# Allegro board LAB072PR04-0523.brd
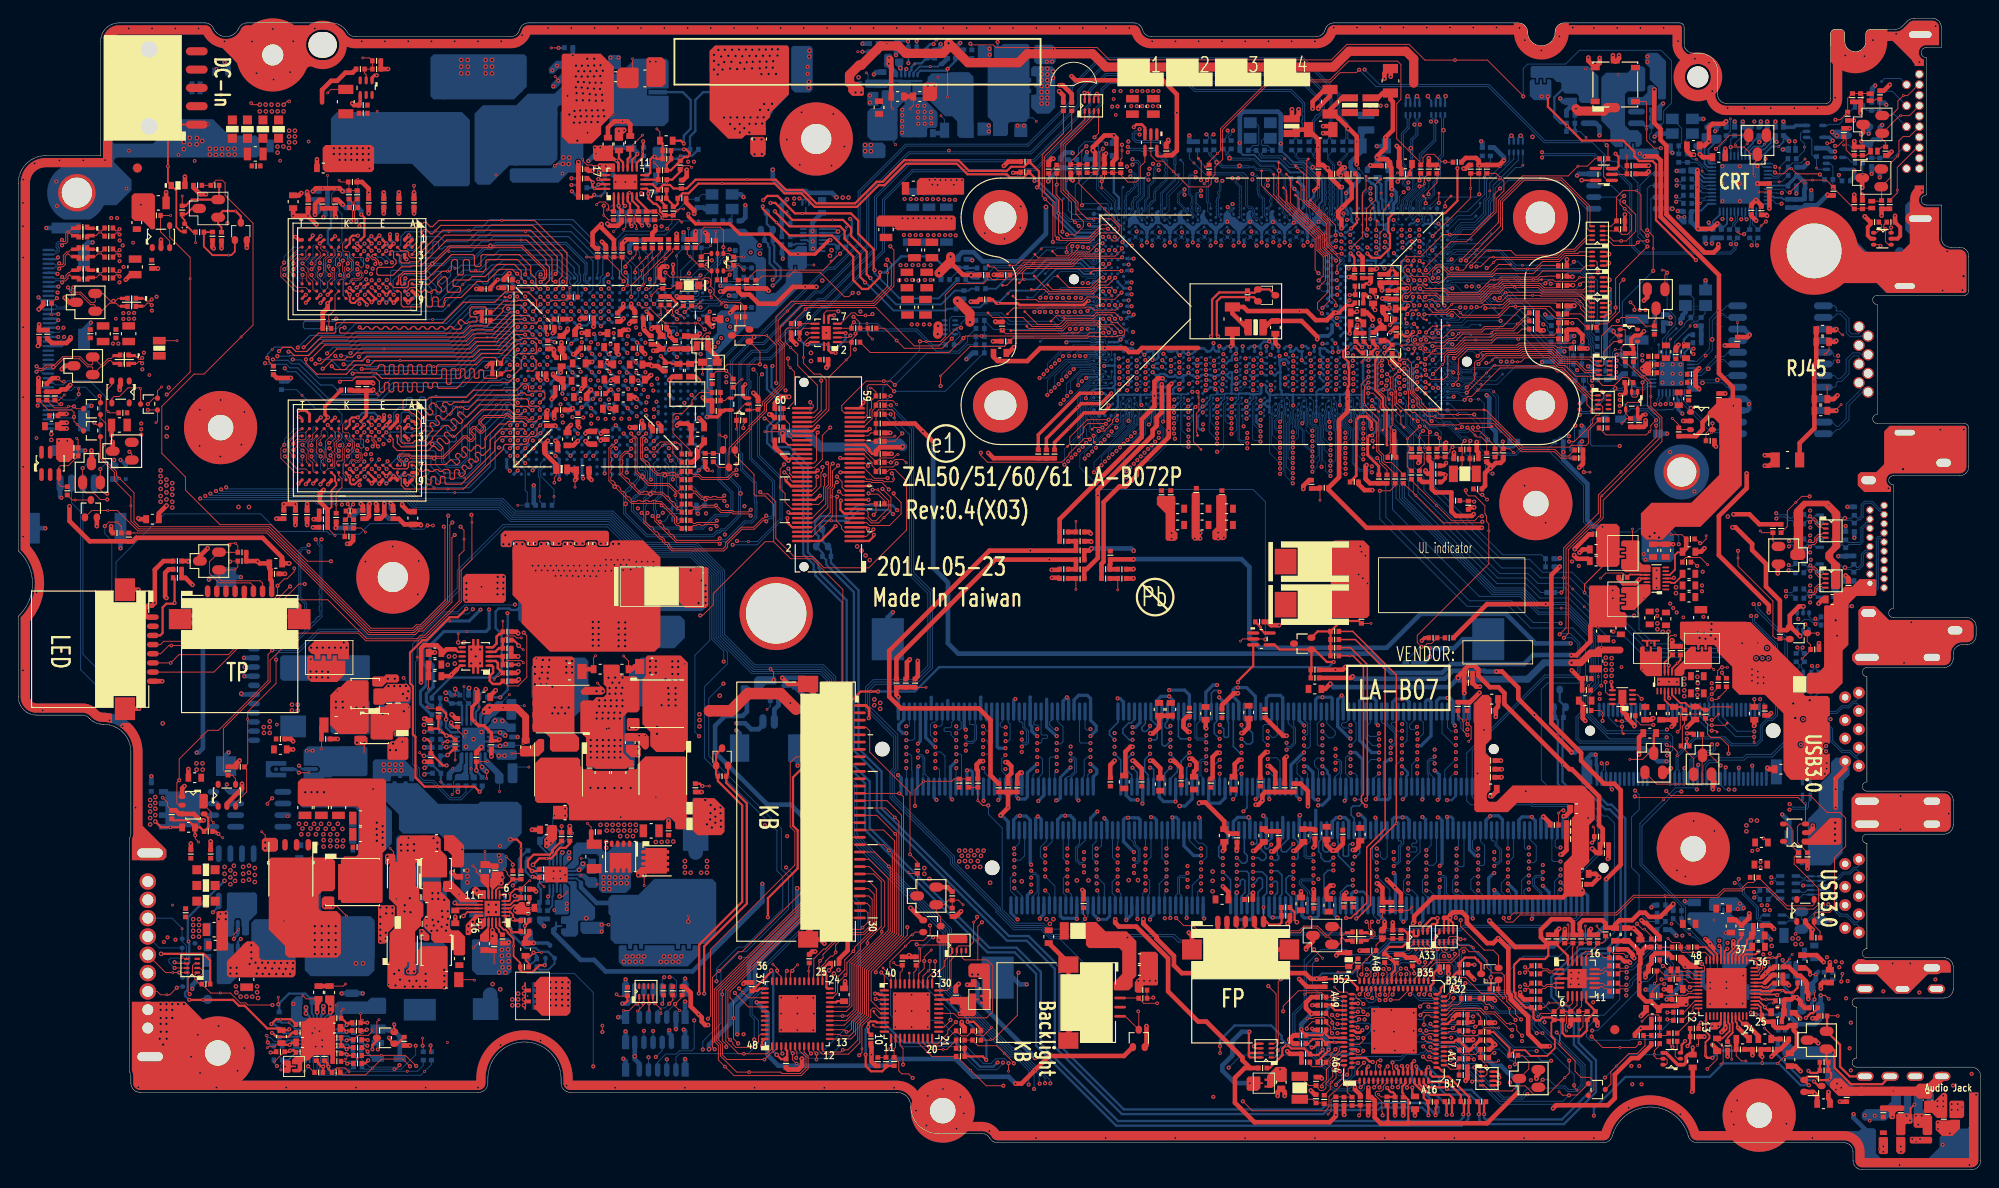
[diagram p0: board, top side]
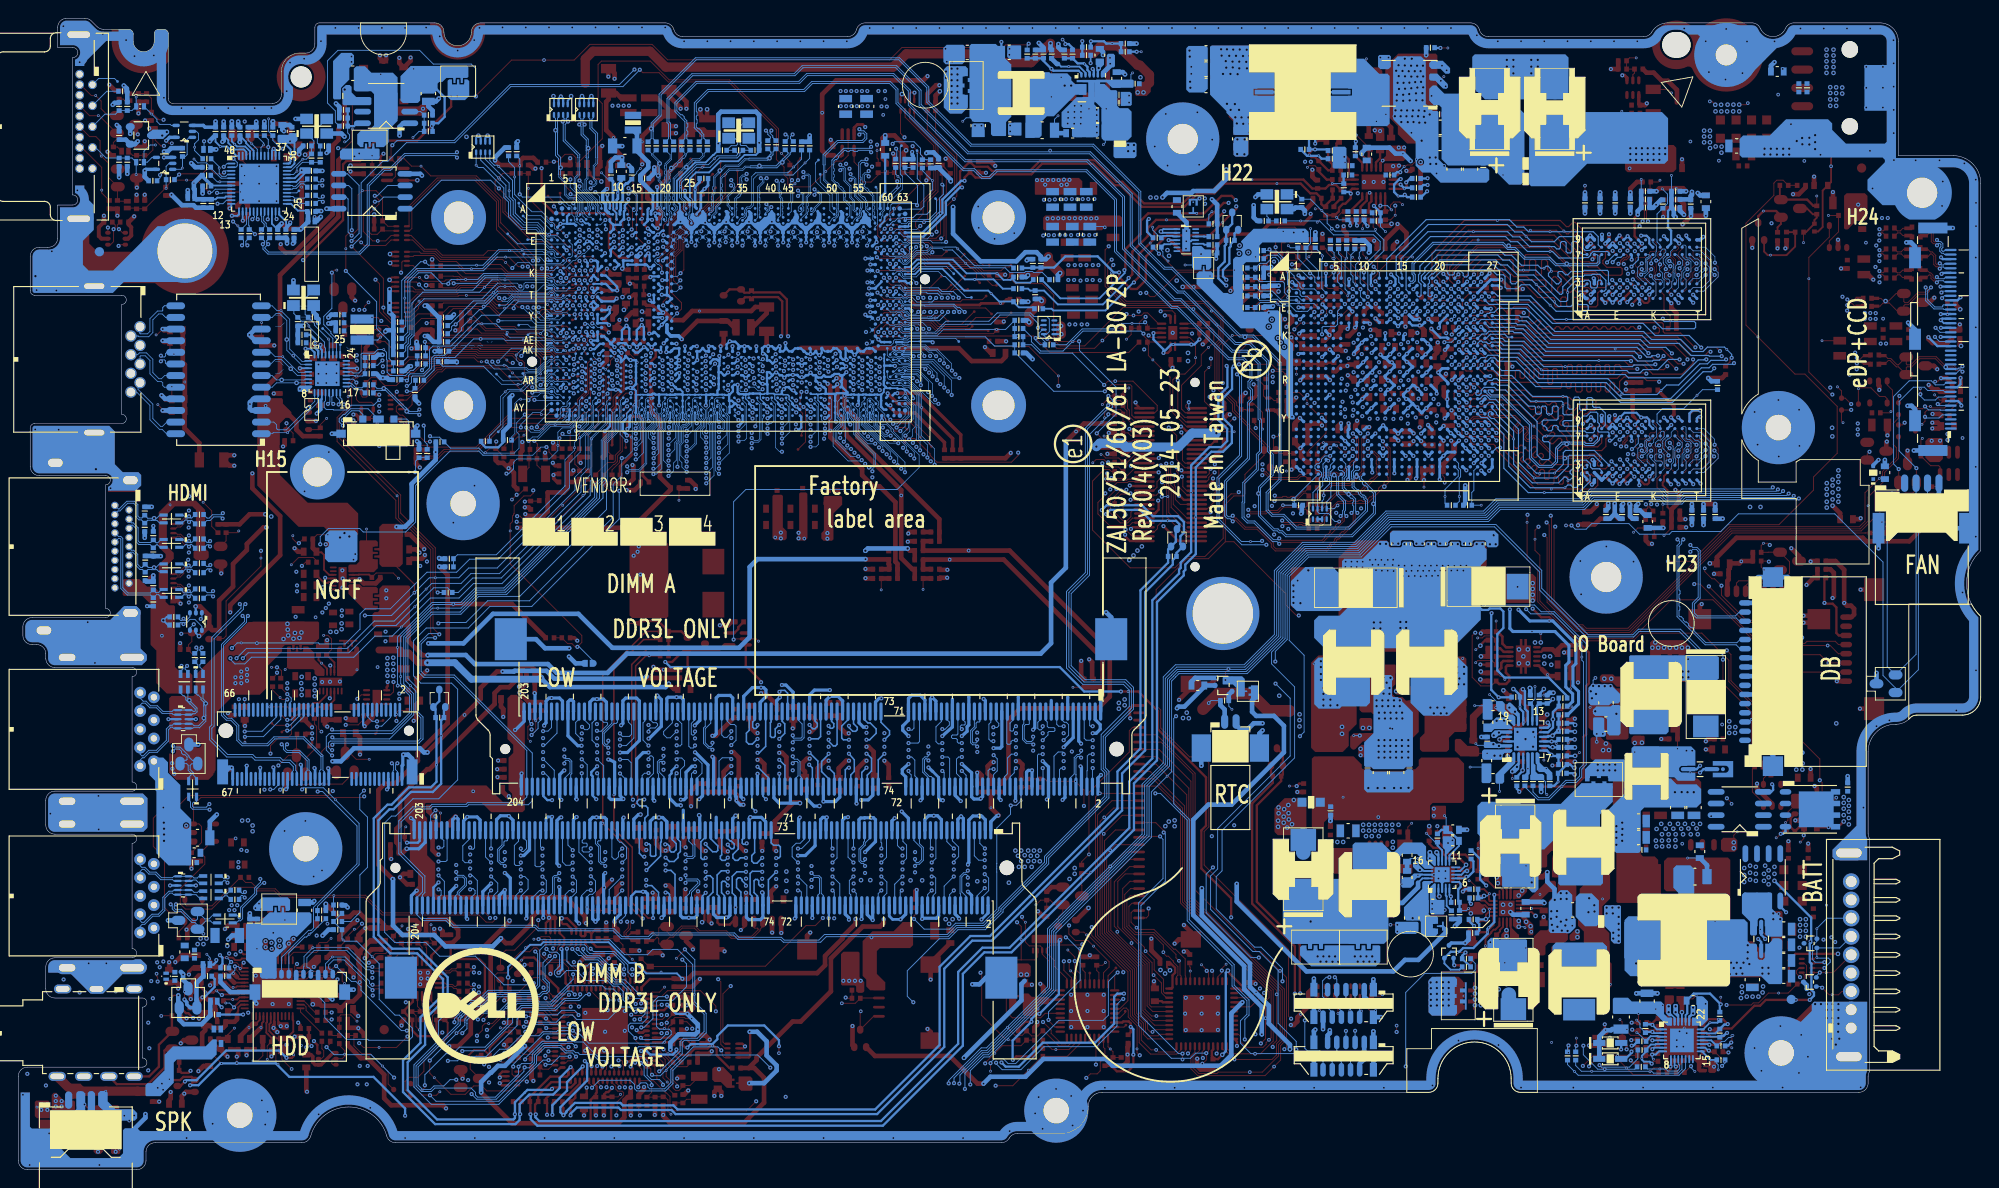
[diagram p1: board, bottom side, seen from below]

Outline 214.4 x 125.75 mm; copper layers: TOP, GND1, IN1, VCC, IN2, IN3, GND2, BOTTOM. Coordinates in mm from the lower left corner of the outline.
Outline path: 0,107.75 arc(0.88,109.87) 3,110.75 9,110.75 9,123.25 arc(9.59,124.66) 11,125.25 20.41,125.25 arc(20.96,125.09) 21.33,124.65 arc(22.7,123.75) 24.07,124.65 arc(24.44,125.09) 24.99,125.25 34.2,125.25 arc(35.2,124.98) 35.93,124.25 arc(36.3,123.88) 36.8,123.75 53.8,123.75 arc(54.41,123.96) 54.77,124.5 arc(55.12,125.04) 55.74,125.25 121.86,125.25 arc(122.48,125.04) 122.83,124.5 arc(123.19,123.96) 123.8,123.75 141.8,123.75 arc(142.41,123.96) 142.77,124.5 arc(143.12,125.04) 143.74,125.25 163.9,125.25 arc(164.61,124.96) 164.9,124.25 arc(166.4,122.75) 167.9,124.25 arc(168.19,124.96) 168.9,125.25 181.5,125.25 arc(181.85,125.1) 182,124.75 182,122.95 arc(182.29,122.24) 183,121.95 183.65,121.95 arc(185.06,121.36) 185.65,119.95 185.65,117.45 arc(185.94,116.74) 186.65,116.45 197.5,116.45 arc(197.85,116.6) 198,116.95 198,124.05 arc(198.15,124.4) 198.5,124.55 199.05,124.55 arc(199.4,124.4) 199.55,124.05 199.55,123.25 arc(200.7,122.1) 201.85,123.25 201.85,124.05 arc(202,124.4) 202.35,124.55 205.09,124.55 arc(205.47,124.63) 205.79,124.84 206.41,125.46 arc(206.73,125.67) 207.11,125.75 209.2,125.75 arc(209.84,125.42) 210.1,124.75 210.1,122.56 208.46,122.56 arc(207.9,122.01) 208.46,121.46 208.46,106.46 arc(207.91,105.91) 208.46,105.36 210.1,105.36 210.1,101.75 arc(210.43,101) 211.2,100.75 212.1,100.75 arc(212.81,100.46) 213.1,99.75 213.1,96 arc(212.95,95.65) 212.6,95.5 203.1,95.5 arc(202.6,95) 203.1,94.5 203.1,82.5 arc(202.6,82) 203.1,81.5 212.6,81.5 arc(212.95,81.35) 213.1,81 213.1,76.8 arc(212.81,76.09) 212.1,75.8 204.85,75.8 arc(204.35,75.3) 204.85,74.8 204.85,61.3 arc(204.35,60.8) 204.85,60.3 212.9,60.3 arc(213.61,60.01) 213.9,59.3 213.9,58.35 arc(213.61,57.64) 212.9,57.35 212.4,57.35 arc(211.69,57.06) 211.4,56.35 211.4,55.85 arc(211.11,55.14) 210.4,54.85 201.97,54.85 arc(201.47,54.35) 201.97,53.85 201.97,42.35 arc(201.47,41.85) 201.97,41.35 210.4,41.35 arc(211.11,41.05) 211.4,40.35 211.4,37.65 arc(211.11,36.94) 210.4,36.65 201.97,36.65 arc(201.47,36.15) 201.97,35.65 201.97,24.15 arc(201.47,23.65) 201.97,23.15 210.4,23.15 arc(211.11,22.85) 211.4,22.15 211.4,19.75 arc(211.11,19.04) 210.4,18.75 200.85,18.75 arc(200.35,18.25) 200.85,17.75 200.85,12.2 arc(200.35,11.7) 200.85,11.2 213.4,11.2 arc(214.11,10.91) 214.4,10.2 214.4,1 arc(214.11,0.29) 213.4,0 201.45,0 arc(200.74,0.29) 200.45,1 200.45,1.95 arc(200.16,2.66) 199.45,2.95 183.41,2.95 arc(182.81,3.16) 182.45,3.69 arc(178.3,6.85) 174.15,3.69 arc(173.79,3.16) 173.19,2.95 107,2.95 arc(106.5,3.08) 106.13,3.45 arc(105.77,3.82) 105.27,3.95 100.5,3.95 arc(98.38,4.83) 97.5,6.95 arc(97.06,8.01) 96,8.45 60.3,8.45 arc(59.59,8.74) 59.3,9.45 59.3,9.95 arc(55.3,13.95) 51.3,9.95 51.3,9.45 arc(51.01,8.74) 50.3,8.45 13.3,8.45 arc(12.59,8.74) 12.3,9.45 12.3,10.18 arc(12.26,10.46) 12.15,10.71 12.15,36.19 arc(12.26,36.44) 12.3,36.72 12.3,45.65 arc(11.42,47.77) 9.3,48.65 9.24,48.65 arc(8.42,48.82) 7.75,49.32 arc(7.41,49.56) 7,49.65 2,49.65 arc(0.59,50.24) 0,51.65 0,60.44 arc(1.55,64.02) 0,67.6 0,107.75

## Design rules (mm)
net group CLK-WLAN: nets CLK_PCIE_WLAN CLK_PCIE_WLAN#
net group CPU_DPB_CTRL: nets CPU_DPB_CTRLCLK CPU_DPB_CTRLDAT
net group CPU_DPB_CTRL_R: nets CPU_DPB_CTRLCLK_R CPU_DPB_CTRLDAT_R
net group CPU_DPC_AUX: nets CPU_DPC_AUX IT6511_AUX_C
net group CPU_DPC_AUX#: nets CPU_DPC_AUX# IT6511_AUX#_C
net group DDI2_LANE_N0: nets DDI2_LANE_N0 IT6511_N0_C
net group DDI2_LANE_N1: nets DDI2_LANE_N1 IT6511_N1_C
net group DDI2_LANE_P0: nets DDI2_LANE_P0 IT6511_P0_C
net group DDI2_LANE_P1: nets DDI2_LANE_P1 IT6511_P1_C
net group DDRA-CTL: nets M_ODT0 M_ODT1
net group DDRB-CTL: nets M_ODT2 M_ODT3
net group DIFFPAIR0: nets EDP_TX0#_C EDP_TX0_C
net group DIFFPAIR1: nets EDP_TX1#_C EDP_TX1_C
net group DIFFPAIR2: nets EDP_AUX#_C EDP_AUX_C
net group DIFFPAIR3: nets CLK_DDC2_CRT_R DAT_DDC2_CRT_R
net group EDP_AUX: nets EDP_AUX EDP_AUX_R
net group EDP_AUX#: nets EDP_AUX# EDP_AUX#_R
net group EDP_TX0: nets EDP_TX0 EDP_TX0_R
net group EDP_TX0#: nets EDP_TX0# EDP_TX0#_R
net group EDP_TX1: nets EDP_TX1 EDP_TX1_R
net group EDP_TX1#: nets EDP_TX1# EDP_TX1#_R
net group FBA-DQS0: nets FBA_RN0 FBA_WP0
net group FBA-DQS1: nets FBA_RN1 FBA_WP1
net group FBA-DQS2: nets FBA_RN2 FBA_WP2
net group FBA-DQS3: nets FBA_RN3 FBA_WP3
net group FBA-DQS4: nets FBA_RN4 FBA_WP4
net group FBA-DQS5: nets FBA_RN5 FBA_WP5
net group FBA-DQS6: nets FBA_RN6 FBA_WP6
net group FBA-DQS7: nets FBA_RN7 FBA_WP7
net group I2C: nets I2C0_SCL I2C0_SDA
net group MDI2: nets MDI2+ MDI2-
net group MDI3: nets MDI3+ MDI3-
net group MDO2: nets MDO2+ MDO2-
net group MDO3: nets MDO3+ MDO3-
net group PCIE-NGFF: nets PCIE_PRX_WLANTX_N4 PCIE_PRX_WLANTX_P4
net group PCIE_PTX_LANRX_N3: nets PCIE_PTX_LANRX_N3 PCIE_PTX_LANRX_N3_C
net group PCIE_PTX_LANRX_P3: nets PCIE_PTX_LANRX_P3 PCIE_PTX_LANRX_P3_C
net group PCIE_PTX_WLANRX_N4: nets PCIE_PTX_WLANRX_N4 PCIE_PTX_WLANRX_N4_C
net group PCIE_PTX_WLANRX_P4: nets PCIE_PTX_WLANRX_P4 PCIE_PTX_WLANRX_P4_C
net group PEG_CRX_GTX_C_N0: nets PEG_CRX_GTX_C_N0 PEG_CRX_GTX_N0
net group PEG_CRX_GTX_C_N1: nets PEG_CRX_GTX_C_N1 PEG_CRX_GTX_N1
net group PEG_CRX_GTX_C_N2: nets PEG_CRX_GTX_C_N2 PEG_CRX_GTX_N2
net group PEG_CRX_GTX_C_N3: nets PEG_CRX_GTX_C_N3 PEG_CRX_GTX_N3
net group PEG_CRX_GTX_C_P0: nets PEG_CRX_GTX_C_P0 PEG_CRX_GTX_P0
net group PEG_CRX_GTX_C_P1: nets PEG_CRX_GTX_C_P1 PEG_CRX_GTX_P1
net group PEG_CRX_GTX_C_P2: nets PEG_CRX_GTX_C_P2 PEG_CRX_GTX_P2
net group PEG_CRX_GTX_C_P3: nets PEG_CRX_GTX_C_P3 PEG_CRX_GTX_P3
net group PEG_CTX_GRX_N0: nets PEG_CTX_GRX_N0 PEG_CTX_GRX_N0_C
net group PEG_CTX_GRX_N1: nets PEG_CTX_GRX_N1 PEG_CTX_GRX_N1_C
net group PEG_CTX_GRX_N2: nets PEG_CTX_GRX_N2 PEG_CTX_GRX_N2_C
net group PEG_CTX_GRX_N3: nets PEG_CTX_GRX_N3 PEG_CTX_GRX_N3_C
net group PEG_CTX_GRX_P0: nets PEG_CTX_GRX_P0 PEG_CTX_GRX_P0_C
net group PEG_CTX_GRX_P1: nets PEG_CTX_GRX_P1 PEG_CTX_GRX_P1_C
net group PEG_CTX_GRX_P2: nets PEG_CTX_GRX_P2 PEG_CTX_GRX_P2_C
net group PEG_CTX_GRX_P3: nets PEG_CTX_GRX_P3 PEG_CTX_GRX_P3_C
net group REM_DIODE3: nets REM_DIODE3_N REM_DIODE3_P
net group REM_DIODE4: nets REM_DIODE4_N REM_DIODE4_P
net group SATA_PRX_DTX_N0: nets SATA_PRX_DTX_N0 SATA_PRX_DTX_N0_R
net group SATA_PRX_DTX_N0_C: nets SATA_PRX_DTX_N0_C SATA_PRX_DTX_N0_RC
net group SATA_PRX_DTX_P0: nets SATA_PRX_DTX_P0 SATA_PRX_DTX_P0_R
net group SATA_PRX_DTX_P0_C: nets SATA_PRX_DTX_P0_C SATA_PRX_DTX_P0_RC
net group SATA_PTX_DRX_N0: nets SATA_PTX_DRX_N0 SATA_PTX_DRX_N0_RC
net group SATA_PTX_DRX_N0_C: nets SATA_PTX_DRX_N0_C SATA_PTX_DRX_N0_R
net group SATA_PTX_DRX_P0: nets SATA_PTX_DRX_P0 SATA_PTX_DRX_P0_RC
net group SATA_PTX_DRX_P0_C: nets SATA_PTX_DRX_P0_C SATA_PTX_DRX_P0_R
net group SPK: nets SPK_L1-_CONN SPK_R2+_CONN
net group USB2-CREADER: nets USB20_CR_N6 USB20_CR_P6
net group USB2-WLAN: nets USB20_MINI1_N4 USB20_MINI1_P4
net group USB2_JUSB0: nets USB20_JUSB1_N0 USB20_JUSB1_P0
net group USB2_JUSB1: nets USB20_JUSB2_N1_R USB20_JUSB2_P1_R
net group USB3R1_JUSB1_R: nets USB3RN1_JUSB1_R USB3RP1_JUSB1_R
net group USB3T1_JUSB1_R: nets USB3TN1_JUSB1_R USB3TP1_JUSB1_R
net group USB3T2_JUSB2_C: nets USB3TN2_JUSB2_C USB3TP2_JUSB2_C
net group USB20_BIO_N3: nets USB20_BIO_N3 USB20_BIO_N3_R
net group USB20_BIO_P3: nets USB20_BIO_P3 USB20_BIO_P3_R
net group USB20_CAM_N7: nets USB20_CAM_N7 USB20_CAM_N7_R
net group USB20_CAM_P7: nets USB20_CAM_P7 USB20_CAM_P7_R
net group USB20_JUSB1_0_R: nets USB20_JUSB1_N0_R USB20_JUSB1_P0_R
net group USB20_JUSB2_1: nets USB20_JUSB2_N1 USB20_JUSB2_P1
net group USB20_JUSB3_2: nets USB20_JUSB3_N2 USB20_JUSB3_P2
net group USB20_TOUCH_N5: nets USB20_TOUCH_N5 USB20_TOUCH_N5_R
net group USB20_TOUCH_P5: nets USB20_TOUCH_P5 USB20_TOUCH_P5_R
net group VRAM-CLKA1: nets CLKA1 CLKA1#
net group VRMA-CLKA0: nets CLKA0 CLKA0#
net group BUS_REM: nets REM_DIODE1_N REM_DIODE1_P REM_DIODE2_N REM_DIODE2_P
net group BUS_RGB: nets BLUE BLUE_CRT CLK_DDC2_CRT DAT_DDC2_CRT GREEN GREEN_CRT HSYNC HSYNC_CONN HSYNC_CRT HSYNC_R RED RED_CRT VSYNC VSYNC_CONN VSYNC_CRT VSYNC_R
net group CLK: nets CLK_PCIE_GFX CLK_PCIE_GFX# CLKOUT_LPC0 XTAL24_IN
net group CLK-33: nets CLK_BIASREF
net group CPU: nets H_CATERR# H_PROCHOT#_R XDP_OBS0_R XDP_OBS1_R XDP_RST#_R
net group CRITICAL: nets DSWODVREN H_CPUPWRGD H_VCCST_PWRGD_XDP PCH_DPWROK PM_APWROK_R SYS_PWROK
net group HDA: nets AUD_HP_OUT_L_CN AUD_HP_OUT_R_CN HPOUT-L HPOUT-R LINE-IN-L LINE-IN-R PCH_AZ_BITCLK PCH_AZ_CODEC_BITCLK PCH_AZ_CODEC_RST# PCH_AZ_CODEC_SDIN0 PCH_AZ_CODEC_SDOUT PCH_AZ_CODEC_SYNC PCH_AZ_RST# PCH_AZ_SDOUT PCH_AZ_SYNC RING2
net group HDA-AUDIO: nets ME_EN N71037 SUSACK#
net group HDMI: nets CPU_DPB_AUX CPU_DPB_AUX# CPU_DPC_CTRLCLK CPU_DPC_CTRLDAT
net group HDMI-DATA: nets DDI1_LANE_N0 DDI1_LANE_N1 DDI1_LANE_N2 DDI1_LANE_P0 DDI1_LANE_P1 DDI1_LANE_P2 TMDS_L_TX0N TMDS_L_TX0P TMDS_L_TX1N TMDS_L_TX1P TMDS_L_TX2N TMDS_L_TX2P TMDS_L_TXCN TMDS_L_TXCP TMDS_TX0N TMDS_TX0P TMDS_TX1N TMDS_TX1P TMDS_TX2N TMDS_TX2P TMDS_TXCN TMDS_TXCP
net group PCIE_COMP: nets PCH_OPI_COMP
net group PWR_10: nets +5V_USB_PWR1
net group PWR_20: nets +1.5VS +1.05VS_AUSB3PLL +3VS_CAM +5VS_KBL +RTCVCC +VCCIO_OUT
net group PWR_40: nets +VDISPLAY_VCC
net group RTC: nets PCH_RTCRST# PCH_RTCX1 PCH_RTCX2 SRTCRST#
net group SENSE: nets VCCSENSE
net group SMBUS: nets MEM_SMBCLK MEM_SMBDATA SML1_SMBCLK
net group SPI: nets PCH_SPI_CLK PCH_SPI_CLK_R PCH_SPI_CS0# PCH_SPI_HOLD1# PCH_SPI_HOLD# PCH_SPI_MISO PCH_SPI_MISO_1 PCH_SPI_MOSI PCH_SPI_MOSI_1 PCH_SPI_WP1# PCH_SPI_WP#
net group SVID: nets ALERT# H_CPU_SVIDALRT# H_CPU_SVIDCLK H_CPU_SVIDDATA H_THERMTRIP# H_THERMTRIP#_R PECI_EC SCLK_CPU SDA_CPU THERMATRIP2# VR_SVID_ALRT# VR_SVID_CLK VR_SVID_DAT
net group USB3-JUSB1: nets USB3RN2_JUSB2_R USB3RP2_JUSB2_R USB3TN2_JUSB2_R USB3TP2_JUSB2_R
net group USB3-JUSB2: nets USB3RN1_JUSB1 USB3RP1_JUSB1 USB3TN1_JUSB1_C USB3TP1_JUSB1_C
net group VRAM-CMD: nets FBA_CMD0 FBA_CMD1 FBA_CMD2 FBA_CMD3 FBA_CMD4 FBA_CMD5 FBA_CMD6 FBA_CMD7 FBA_CMD8 FBA_CMD9 FBA_CMD10 FBA_CMD11 FBA_CMD12 FBA_CMD13 FBA_CMD14 FBA_CMD15 FBA_CMD16 FBA_CMD17 FBA_CMD18 FBA_CMD19 FBA_CMD20 FBA_CMD21 FBA_CMD22 FBA_CMD23 FBA_CMD24 FBA_CMD25 FBA_CMD26 FBA_CMD27 FBA_CMD28 FBA_CMD29 FBA_CMD30 FBA_CMD31
net group VRAM-DQ: nets FBA_D0 FBA_D1 FBA_D2 FBA_D3 FBA_D4 FBA_D5 FBA_D6 FBA_D7 FBA_D8 FBA_D9 FBA_D10 FBA_D11 FBA_D12 FBA_D13 FBA_D14 FBA_D15 FBA_D16 FBA_D17 FBA_D18 FBA_D19 FBA_D20 FBA_D21 FBA_D22 FBA_D23 FBA_D24 FBA_D25 FBA_D26 FBA_D27 FBA_D28 FBA_D29 FBA_D30 FBA_D31 FBA_D32 FBA_D33 FBA_D34 FBA_D35 FBA_D36 FBA_D37 FBA_D38 FBA_D39 FBA_D40 FBA_D41 FBA_D42 FBA_D43 FBA_D44 FBA_D45 FBA_D46 FBA_D47 FBA_D48 FBA_D49 FBA_D50 FBA_D51 FBA_D52 FBA_D53 FBA_D54 FBA_D55 FBA_D56 FBA_D57 FBA_D58 FBA_D59 FBA_D60 FBA_D61 FBA_D62 FBA_D63 FBA_DQM0 FBA_DQM1 FBA_DQM2 FBA_DQM3 FBA_DQM4 FBA_DQM5 FBA_DQM6 FBA_DQM7
nets with their own width: min track width 0.508; nets GND

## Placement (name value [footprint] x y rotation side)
C7  10U_0603_6.3V6M  [C_0603]  10.47 75.43 90 bottom
C35  2.2U_0402_6.3V6M  [C_0402]  131.5 74.17 270 top
C36  2.2U_0402_6.3V6M  [C_0402]  128.71 74.42 270 top
C37  2.2U_0402_6.3V6M  [C_0402]  125.91 74.17 270 top
C38  2.2U_0402_6.3V6M  [C_0402]  124.9 74.17 270 top
C39  10U_0603_6.3V6M  [C_0603]  132.71 70.41 180 top
C40  22U_0603_6.3V6M  [C_0603]  107.94 89.21 180 top
C41  10U_0603_6.3V6M  [C_0603]  132.71 72.19 180 top
C42  10U_0603_6.3V6M  [C_0603]  130.04 70.41 180 top
C43  22U_0603_6.3V6M  [C_0603]  137.34 92.7 270 top
C44  22U_0603_6.3V6M  [C_0603]  148.01 94.6 90 top
C45  10U_0603_6.3V6M  [C_0603]  127.37 70.41 180 top
C50  1U_0402_6.3V6K  [C_0402]  148.77 97.79 270 top
C51  1U_0402_6.3V6K  [C_0402]  150.09 90.07 270 top
C52  0.1U_0402_10V7K  [C_0402]  150.55 91.04 90 top
C53  1U_0402_6.3V6K  [C_0402]  150.55 97.79 270 top
C54  1U_0402_6.3V6K  [C_0402]  154.41 76 0 top
C55  0.1U_0402_10V7K  [C_0402]  154.41 76.89 0 top
C56  0.1U_0402_10V7K  [C_0402]  154.41 75.11 0 top
C57  1U_0402_6.3V6K  [C_0402]  149.66 97.79 270 top
C58  1U_0402_6.3V6K  [C_0402]  146.44 108.26 180 bottom
C59  100U_1206_6.3V6M  [C_1206]  146.8 111.81 0 bottom
C60  10U_0603_6.3V6M  [C_0603]  145.56 93.63 0 top
C61  1U_0402_6.3V6K  [C_0402]  147.02 90.45 90 top
C62  1U_0402_6.3V6K  [C_0402]  146.13 90.45 90 top
C63  1U_0402_6.3V6K  [C_0402]  149.86 109.65 180 top
C64  1U_0402_6.3V6K  [C_0402]  141.28 74.4 90 top
C65  100U_1206_6.3V6M  [C_1206]  149.92 117.59 90 top
C66  22U_0603_6.3V6M  [C_0603]  152.26 109.84 180 top
C67  1U_0402_6.3V6K  [C_0402]  152.02 108.77 180 top
C68  0.1U_0402_10V7K  [C_0402]  149.66 96.01 270 top
C69  1U_0402_6.3V6K  [C_0402]  146.03 94.67 0 top
C70  100U_1206_6.3V6M  [C_1206]  132.64 94.22 270 top
C71  0.1U_0402_10V7K  [C_0402]  150.55 96.01 270 top
C72  10U_0603_6.3V6M  [C_0603]  130.04 72.19 180 top
C73  1U_0402_6.3V6K  [C_0402]  147.76 98.3 270 top
C74  10U_0603_6.3V6M  [C_0603]  127.37 72.19 180 top
C76  1U_0402_6.3V6K  [C_0402]  146.08 95.56 0 top
C77  0.1U_0402_10V7K  [C_0402]  147.83 89.21 180 top
C78  22U_0603_6.3V6M  [C_0603]  145.56 92.43 0 top
C80  0.1U_0402_10V7K  [C_0402]  114.99 109.78 270 top
C81  0.1U_0402_10V7K  [C_0402]  150.37 92.89 180 top
C82  22U_0603_6.3V6M  [C_0603]  150.49 94.03 180 top
C83  1U_0402_6.3V6K  [C_0402]  146 98.3 270 top
C84  100U_1206_6.3V6M  [C_1206]  143.31 115.31 90 top
C85  1U_0402_6.3V6K  [C_0402]  143.36 108.77 0 top
C86  100U_1206_6.3V6M  [C_1206]  140.96 113.59 0 top
C87  1U_0402_6.3V6K  [C_0402]  146.87 98.3 270 top
C88  1U_0402_6.3V6K  [C_0402]  146.03 96.5 0 top
C1160  0.1U_0402_10V7K  [C_0402]  102.04 28.58 270 top
C1313  0.47U_0402_10V4  [C_0402]  172.85 69.4 180 top
C2305  10U_0603_6.3V6M  [C_0603]  182.75 52.03 0 top
C2306  10U_0603_6.3V6M  [C_0603]  182.74 53.9 0 top
C2307  10U_0805_10V4Z  [C_0805]  183.83 59.46 90 top
C2308  10U_0603_6.3V6M  [C_0603]  193.29 43.74 180 top
C2309  0.01U_0603_25V7K  [C_0603]  183.19 50.57 270 top
C2310  10U_0805_10V4Z  [C_0805]  173.22 59.68 270 top
C2311  10U_0603_6.3V6M  [C_0603]  181.82 63.81 0 top
C2312  10U_0603_6.3V6M  [C_0603]  175.09 59.87 270 top
C2313  10U_0603_6.3V6M  [C_0603]  181.82 62.54 0 top
C2314  0.01U_0603_25V7K  [C_0603]  181.82 65.08 0 top
C2315  10U_0603_6.3V6M  [C_0603]  178.59 66.92 90 top
C2316  10U_0603_6.3V6M  [C_0603]  179.51 50.54 270 top
C2317  10U_0603_6.3V6M  [C_0603]  179.98 66.92 90 top
C2318  10U_0603_6.3V6M  [C_0603]  177.75 50.54 270 top
C2322  0.01U_0603_25V7K  [C_0603]  180.9 50.54 270 top
C2323  10U_0603_6.3V6M  [C_0603]  180.02 59.46 90 top
C2324  10U_0603_6.3V6M  [C_0603]  178.24 59.56 90 top
C2325  0.01U_0603_25V7K  [C_0603]  181.82 67.49 0 top
C2326  68P_0402_50V8J  [C_0402]  173.42 87.24 180 bottom
C2327  0.1U_0402_10V7K  [C_0402]  168.41 93.08 180 bottom
C2328  10U_0603_6.3V6M  [C_0603]  173.09 66.47 180 top
C2329  10U_0603_6.3V6M  [C_0603]  173.09 67.74 180 top
C4311  0.1U_0402_10V7K  [C_0402]  9.43 101.96 0 top
C4312  0.1U_0402_10V7K  [C_0402]  9.43 102.85 0 top
C4313  0.1U_0402_10V7K  [C_0402]  9.43 99.67 0 top
C4314  0.1U_0402_10V7K  [C_0402]  9.43 100.56 0 top
C4321  0.1U_0402_10V7K  [C_0402]  9.43 98.27 0 top
C4322  0.1U_0402_10V7K  [C_0402]  9.43 97.39 0 top
C5212  68P_0402_50V8J  [C_0402]  105.67 94.8 180 bottom
C5254  0.1U_0402_25V6K  [C_0402]  88.75 22.53 0 top
C5255  0.1U_0402_25V6K  [C_0402]  80.14 19.53 90 top
C5256  0.1U_0402_25V6K  [C_0402]  83.88 12.07 270 top
C5259  4.7U_0603_6.3V6K  [C_0603]  90.23 18.4 90 top
C5261  1U_0603_10V6K  [C_0603]  112.58 26.15 270 top
C5262  10U_0603_6.3V6M  [C_0603]  121.78 21.77 0 top
C5263  1U_0603_10V6K  [C_0603]  121.78 23.04 0 top
C5291  2200P_0402_25V7K  [C_0402]  175.77 64.7 180 top
C5292  2200P_0402_25V7K  [C_0402]  180.71 56.24 90 top
C5293  2200P_0402_25V7K  [C_0402]  181.6 56.24 90 top
CA21  22P_0402_50V8J  [C_0402]  179.96 28.91 180 bottom
CA22  22P_0402_50V8J  [C_0402]  179.33 22.91 180 top
CA23  2.2U_0402_6.3V6M  [C_0402]  192.9 18.44 180 top
CA24  1U_0402_6.3V6K  [C_0402]  192.31 22.04 180 bottom
CA25  1U_0402_6.3V6K  [C_0402]  192.31 21.14 180 bottom
CA26  22P_0402_50V8J  [C_0402]  103.56 98.53 90 bottom
CA29  1000P_0402_50V7K  [C_0402]  203.76 5.77 90 top
CA30  1000P_0402_50V7K  [C_0402]  205.67 5.77 90 top
CA31  1000P_0402_50V7K  [C_0402]  208.59 5.55 90 top
CA32  1000P_0402_50V7K  [C_0402]  210.37 5.06 90 top
CA33  100P_0402_50V8J  [C_0402]  193.43 16.94 180 bottom
CA38  690P_0402_50V8J  [C_0402]  199.75 8.35 270 top
CA39  100P_0402_50V8J  [C_0402]  194.19 21.14 180 bottom
CA40  690P_0402_50V8J  [C_0402]  197.3 20.66 90 bottom
CA51  0.1U_0402_10V7K  [C_0402]  191.75 16.16 0 top
CA53  10U_0603_6.3V6M  [C_0603]  187.13 25.9 90 top
CA54  0.1U_0402_10V7K  [C_0402]  188.27 25.76 90 top
CA55  10U_0603_6.3V6M  [C_0603]  183.25 26.85 180 top
CA56  0.1U_0402_10V7K  [C_0402]  183.39 24.31 180 top
CA57  4.7U_0603_6.3V6K  [C_0603]  177.22 23.74 90 top
CA58  0.1U_0402_10V7K  [C_0402]  181.61 23.17 180 top
CA59  4.7U_0603_6.3V6K  [C_0603]  179.23 17.54 180 top
CA60  0.1U_0402_10V7K  [C_0402]  181.61 18.6 180 top
CA61  4.7U_0603_6.3V6K  [C_0603]  189.4 25.58 0 top
CA62  10U_0603_6.3V6M  [C_0603]  192.9 17.2 180 top
CA63  10U_0603_6.3V6M  [C_0603]  190.82 24.34 180 top
CA64  10U_0603_6.3V6M  [C_0603]  180.46 19.74 0 top
CA65  0.1U_0402_10V7K  [C_0402]  181.23 14.91 180 top
CA67  4.7U_0603_6.3V6K  [C_0603]  190.11 14.28 0 top
CA68  4.7U_0603_6.3V6K  [C_0603]  189.09 14.28 180 top
CA69  100P_0402_50V8J  [C_0402]  179.33 15.55 180 top
CA71  10U_0603_6.3V6M  [C_0603]  193.98 15.74 90 top
CA74  10U_0603_6.3V6M  [C_0603]  185.6 14.34 270 top
CA75  0.1U_0402_10V7K  [C_0402]  197.74 11.74 180 top
CA76  1U_0402_6.3V6K  [C_0402]  178.41 25.2 0 top
CA77  4.7U_0603_6.3V6K  [C_0603]  175.66 25 90 top
CC1  15P_0402_50V8J  [C_0402]  159.52 77.65 180 top
CC2  15P_0402_50V8J  [C_0402]  156.82 77.65 0 top
CC3  1U_0402_6.3V6K  [C_0402]  158.42 72.11 90 top
CC4  1U_0402_6.3V6K  [C_0402]  154.11 58.09 0 top
CC5  27P_0402_50V8J  [C_0402]  179.04 26.22 0 bottom
CC6  15P_0402_50V8J  [C_0402]  133.46 111.34 0 bottom
CC7  15P_0402_50V8J  [C_0402]  137.93 111.34 180 bottom
CC8  0.022U_0402_16V7K  [C_0402]  118.34 64.57 0 top
CC9  0.022U_0402_16V7K  [C_0402]  113.77 69.65 0 top
CC10  0.022U_0402_16V7K  [C_0402]  116.46 64.57 180 top
CC11  0.1U_0402_10V7K  [C_0402]  177.09 82.04 270 top
CC13  0.1U_0402_10V7K  [C_0402]  87.56 88.48 0 top
CC14  0.1U_0402_10V7K  [C_0402]  93.7 78.18 0 top
CC15  0.1U_0402_10V7K  [C_0402]  83.57 79.68 180 top
CC16  0.1U_0402_10V7K  [C_0402]  93.71 80.48 0 top
CC17  0.1U_0402_10V7K  [C_0402]  83.57 82.13 180 top
CC18  0.22U_0402_16V7K  [C_0402]  141.03 111.36 90 bottom
CC19  0.22U_0402_16V7K  [C_0402]  141.91 111.36 90 bottom
CC20  0.22U_0402_16V7K  [C_0402]  139.12 111.36 90 bottom
CC21  0.22U_0402_16V7K  [C_0402]  140.01 111.36 90 bottom
CC22  0.22U_0402_16V7K  [C_0402]  144.71 111.36 90 bottom
CC23  0.22U_0402_16V7K  [C_0402]  145.6 111.36 90 bottom
CC24  0.22U_0402_16V7K  [C_0402]  142.8 111.36 90 bottom
CC25  0.22U_0402_16V7K  [C_0402]  143.69 111.36 90 bottom
CC26  1U_0603_10V6K  [C_0603]  84.83 52.89 0 bottom
CC27  100P_0402_50V8J  [C_0402]  117.53 109.45 90 bottom
CC28  100P_0402_50V8J  [C_0402]  113.85 109.45 90 bottom
CC29  0.1U_0402_10V7K  [C_0402]  85.35 91.4 180 top
CC31  0.047U_0402_16V4Z  [C_0402]  171.06 85.35 270 bottom
CC32  0.1U_0402_10V7K  [C_0402]  130.61 112.3 270 bottom
CC33  0.047U_0402_16V4Z  [C_0402]  176.41 85.97 180 top
CC34  0.047U_0402_16V4Z  [C_0402]  155.88 77.83 90 top
CC35  0.047U_0402_16V4Z  [C_0402]  149.53 75.88 270 top
CC40  0.1U_0402_10V7K  [C_0402]  129.72 112.3 270 bottom
CC41  0.1U_0402_25V6  [C_0402]  125.4 110.8 90 top
CC42  100P_0402_50V8J  [C_0402]  118.67 108.89 90 top
CD1  2.2U_0402_6.3V6M  [C_0402]  96.96 52.68 90 top
CD2  0.1U_0402_10V7K  [C_0402]  97.97 52.68 90 top
CD3  0.1U_0402_10V7K  [C_0402]  104.83 41.76 90 top
CD4  1U_0402_6.3V6K  [C_0402]  119.31 41.89 90 top
CD5  1U_0402_6.3V6K  [C_0402]  122.74 41.89 90 top
CD6  1U_0402_6.3V6K  [C_0402]  127.06 42.01 90 top
CD7  1U_0402_6.3V6K  [C_0402]  130.29 41.76 90 top
CD8  1U_0402_6.3V6K  [C_0402]  135.69 41.89 90 top
CD9  1U_0402_6.3V6K  [C_0402]  136.2 50.29 270 top
CD10  1U_0402_6.3V6K  [C_0402]  127.94 50.42 270 top
CD11  1U_0402_6.3V6K  [C_0402]  131.5 49.38 90 top
CD12  10U_0603_6.3V6M  [C_0603]  124.64 50.98 270 top
CD13  10U_0603_6.3V6M  [C_0603]  125.91 50.98 270 top
CD14  10U_0603_6.3V6M  [C_0603]  129.72 50.54 270 top
CD15  330U_D3_2.5VY_R6M  [C_D3]  138.46 61.71 0 top
CD16  10U_0603_6.3V6M  [C_0603]  120.83 41.65 90 top
CD17  10U_0603_6.3V6M  [C_0603]  124.77 41.39 90 top
CD18  10U_0603_6.3V6M  [C_0603]  128.45 41.52 90 top
CD19  10U_0603_6.3V6M  [C_0603]  132.77 41.52 90 top
CD20  10U_0603_6.3V6M  [C_0603]  134.42 50.66 270 top
CD21  2.2U_0402_6.3V6M  [C_0402]  137.34 41.25 90 top
CD22  0.1U_0402_10V7K  [C_0402]  138.36 41.25 90 top
CD23  0.1U_0402_10V7K  [C_0402]  135.16 59.83 0 top
CD24  0.1U_0402_10V7K  [C_0402]  160.51 50.12 0 top
CD25  0.1U_0402_10V7K  [C_0402]  160.41 44.68 0 top
CD26  0.1U_0402_10V7K  [C_0402]  160.38 43.74 0 top
CD27  0.1U_0402_10V7K  [C_0402]  160.38 42.85 0 top
CD28  10U_0603_6.3V6M  [C_0603]  160.27 51.39 0 top
CD29  10U_0603_6.3V6M  [C_0603]  160.14 41.58 0 top
CD30  2.2U_0402_6.3V6M  [C_0402]  157.97 53.17 0 top
CD31  0.1U_0402_10V7K  [C_0402]  157.97 54.19 0 top
CD32  2.2U_0402_6.3V6M  [C_0402]  109.15 41.25 90 top
CD33  0.1U_0402_10V7K  [C_0402]  108.13 41.25 90 top
CD34  0.1U_0402_10V7K  [C_0402]  116.39 28.62 90 top
CD35  1U_0402_6.3V6K  [C_0402]  133.96 29.52 0 top
CD36  1U_0402_6.3V6K  [C_0402]  141.53 28.55 90 top
CD37  1U_0402_6.3V6K  [C_0402]  144.84 28.68 90 top
CD38  1U_0402_6.3V6K  [C_0402]  145.85 28.68 90 top
CD39  1U_0402_6.3V6K  [C_0402]  133.15 36.71 270 top
CD40  1U_0402_6.3V6K  [C_0402]  137.72 36.96 270 top
CD41  1U_0402_6.3V6K  [C_0402]  141.66 37.09 270 top
CD42  1U_0402_6.3V6K  [C_0402]  144.71 37.09 270 top
CD43  10U_0603_6.3V6M  [C_0603]  136.07 37.2 270 top
CD44  10U_0603_6.3V6M  [C_0603]  131.75 37.2 270 top
CD45  10U_0603_6.3V6M  [C_0603]  140.39 37.2 270 top
CD46  10U_0603_6.3V6M  [C_0603]  130.8 29.52 0 top
CD47  10U_0603_6.3V6M  [C_0603]  146.61 37.33 270 top
CD48  10U_0603_6.3V6M  [C_0603]  142.93 37.45 270 top
CD49  10U_0603_6.3V6M  [C_0603]  140.14 28.34 90 top
CD50  10U_0603_6.3V6M  [C_0603]  143.18 28.18 90 top
CD51  330U_D3_2.5VY_R6M  [C_D3]  138.46 66.41 0 top
CD52  2.2U_0402_6.3V6M  [C_0402]  149.03 28.3 90 top
CD53  0.1U_0402_10V7K  [C_0402]  150.04 28.3 90 top
CD54  0.1U_0402_10V7K  [C_0402]  170.06 37.9 180 top
CD55  0.1U_0402_10V7K  [C_0402]  170.06 37.01 180 top
CD56  0.1U_0402_10V7K  [C_0402]  170.06 36.12 180 top
CD57  0.1U_0402_10V7K  [C_0402]  170.41 31.17 0 top
CD58  10U_0603_6.3V6M  [C_0603]  170.17 32.31 0 top
CD59  10U_0603_6.3V6M  [C_0603]  170.93 39.42 180 top
CD60  2.2U_0402_6.3V6M  [C_0402]  172.83 35.49 0 top
CD61  0.1U_0402_10V7K  [C_0402]  172.83 34.6 0 top
CD62  22U_0603_6.3V6M  [C_0603]  142.36 52.5 180 top
CD64  0.1U_0402_10V7K  [C_0402]  146.74 59.67 90 top
CE3  0.1U_0402_25V6  [C_0402]  93.15 14.73 270 top
CE4  10U_0603_6.3V6M  [C_0603]  105.78 20.37 180 top
CE10  0.1U_0402_25V6  [C_0402]  102.42 18.6 90 top
CE13  0.047U_0402_16V4Z  [C_0402]  159.74 13.13 0 top
CE14  1U_0402_6.3V6K  [C_0402]  157.41 14.15 0 top
CE17  1U_0402_6.3V6K  [C_0402]  140.67 14.68 180 top
CE21  1U_0402_6.3V6K  [C_0402]  146.61 7.04 90 top
CE24  0.01U_0402_16V7K  [C_0402]  11.24 69.55 180 top
CE38  0.1U_0402_25V6  [C_0402]  142.88 17.96 180 top
CE39  2200P_0402_50V7K  [C_0402]  160.34 7.43 180 top
CE40  0.1U_0402_25V6  [C_0402]  150.55 22.58 90 top
CE41  0.1U_0402_25V6  [C_0402]  157.41 16.94 0 top
CE42  10U_0603_6.3V6M  [C_0603]  137.98 10.28 270 top
CE43  0.1U_0402_25V6  [C_0402]  151.31 7.93 270 top
CE44  0.1U_0402_25V6  [C_0402]  155.3 22.15 0 top
CE45  4.7U_0603_6.3V6K  [C_0603]  152.59 8 270 top
CE46  0.1U_0402_25V6  [C_0402]  147.5 7.93 270 top
CE47  100P_0402_50V8J  [C_0402]  134.29 95.1 90 top
CE48  100P_0402_50V8J  [C_0402]  87.86 66.98 0 bottom
CE49  1U_0402_6.3V6K  [C_0402]  144.84 7.93 270 top
CE50  0.1U_0402_25V6  [C_0402]  142.77 20.89 270 top
CE51  100P_0402_50V8J  [C_0402]  81.53 101.5 0 bottom
CE52  4.7P_0402_50V8C  [C_0402]  159.69 18.72 0 top
CE53  27P_0402_50V8J  [C_0402]  141.79 7.29 90 top
CE54  4700P_0402_25V7K  [C_0402]  150.42 7.93 270 top
CE55  0.1U_0402_25V6  [C_0402]  157.41 11.23 0 top
CE58  2200P_0402_50V7K  [C_0402]  154.94 7.42 180 top
CE59  1U_0402_6.3V6K  [C_0402]  148.34 23.93 180 top
CE60  2200P_0402_50V7K  [C_0402]  157.6 7.44 0 top
CE61  0.1U_0402_25V6  [C_0402]  157.46 21.52 0 top
CE62  22P_0402_50V8J  [C_0402]  141.79 9.2 90 top
CE63  0.1U_0402_25V6  [C_0402]  159.74 14.15 0 top
CE64  0.1U_0402_25V6  [C_0402]  142.88 15.27 180 top
CE65  0.1U_0402_25V6  [C_0402]  141.1 12.63 180 top
CE66  100P_0402_50V8J  [C_0402]  168.81 49.38 180 bottom
CE68  1U_0402_6.3V6K  [C_0402]  27.54 65.08 0 top
CE69  100P_0402_50V8J  [C_0402]  76.43 42.98 0 top
CE70  2200P_0402_50V7K  [C_0402]  155.85 7.44 0 top
CI1  100U_1206_6.3V6M  [C_1206]  196.14 36.25 180 bottom
CI2  0.1U_0402_10V7K  [C_0402]  195.81 33.54 180 bottom
CI3  0.1U_0402_10V7K  [C_0402]  195.13 55.48 90 bottom
CI4  0.1U_0402_10V7K  [C_0402]  194.24 55.48 90 bottom
CI6  1U_0603_10V6K  [C_0603]  191.08 33.33 180 top
CI8  100U_1206_6.3V6M  [C_1206]  192.9 25.58 180 bottom
CI9  0.1U_0402_10V7K  [C_0402]  195.15 23.99 270 bottom
CI10  0.1U_0402_10V7K  [C_0402]  191.19 30.53 180 bottom
CI11  0.1U_0402_10V7K  [C_0402]  191.19 29.52 180 bottom
CI12  1U_0603_10V6K  [C_0603]  191.15 35.74 180 top
CI13  0.1U_0402_10V7K  [C_0402]  194.49 34.62 270 top
CI15  0.1U_0402_10V7K  [C_0402]  195.48 34.62 270 top
CI17  0.1U_0402_10V7K  [C_0402]  196.85 25.33 180 top
CI26  0.1U_0402_10V7K  [C_0402]  190.12 31.93 180 top
CI40  10U_0603_6.3V6M  [C_0603]  195.9 34.61 180 bottom
CI43  10U_0603_6.3V6M  [C_0603]  196.22 24.49 270 bottom
CI44  1U_0603_10V6K  [C_0603]  19.98 42.81 180 top
CI46  0.1U_0402_10V7K  [C_0402]  22.92 43.09 90 top
CI47  0.1U_0402_10V7K  [C_0402]  24.71 44 180 top
CI48  0.1U_0402_10V7K  [C_0402]  28.17 47.04 0 top
CI49  10U_0603_6.3V6M  [C_0603]  27.93 45.9 0 top
CI50  1U_0402_6.3V6K  [C_0402]  167.16 24.74 90 top
CL15  0.1U_0402_10V7K  [C_0402]  182.95 90.31 0 bottom
CL19  0.1U_0402_10V7K  [C_0402]  182.49 84.05 90 top
CL20  0.1U_0402_10V7K  [C_0402]  183.25 86.87 180 top
CL21  0.1U_0402_10V7K  [C_0402]  178.1 88.83 0 top
CL22  0.1U_0402_10V7K  [C_0402]  183.25 85.98 180 top
CL24  0.1U_0402_10V7K  [C_0402]  178.81 92.5 0 bottom
CL25  4.7U_0402_6.3V6M  [C_0402]  178.81 93.39 0 bottom
CL26  0.1U_0402_10V7K  [C_0402]  181.09 89.47 270 top
CL30  0.1U_0402_10V7K  [C_0402]  175.61 84.84 0 bottom
CL31  0.1U_0402_10V7K  [C_0402]  175.61 85.73 0 bottom
CL33  10P_1206_2KV8J  [C_1206]  194.62 77.52 180 top
CL34  0.1U_0402_10V7K  [C_0402]  178.1 87.94 0 top
CL35  1U_0402_6.3V6K  [C_0402]  178.1 87.05 0 top
CL36  10P_0402_50V8J  [C_0402]  183.86 92.17 90 bottom
CL37  10P_0402_50V8J  [C_0402]  181.82 93.09 0 bottom
CL39  1U_0402_6.3V6K  [C_0402]  185.79 83.86 90 top
CL41  0.01U_0402_16V7K  [C_0402]  187.82 90.02 90 top
CL42  0.1U_0402_10V7K  [C_0402]  178.81 91.61 0 bottom
CL43  4.7U_0603_6.3V6K  [C_0603]  182.21 90.03 270 top
CL44  4.7U_0603_6.3V6K  [C_0603]  181.41 83.49 90 top
CL45  4.7U_0603_6.3V6K  [C_0603]  180.01 90.03 270 top
CM1  0.1U_0402_10V7K  [C_0402]  131.63 111.48 90 bottom
CM2  0.1U_0402_10V7K  [C_0402]  132.52 111.48 90 bottom
CM3  0.1U_0402_10V7K  [C_0402]  170.92 53.65 0 top
CM4  22U_0603_6.3V6M  [C_0603]  171.89 51.23 180 top
CM5  0.1U_0402_10V7K  [C_0402]  171.77 52.38 180 top
CM6  22U_0603_6.3V6M  [C_0603]  189.67 50.54 270 top
CM7  0.1U_0402_10V7K  [C_0402]  190.81 50.55 270 top
CM8  2200P_0402_25V7K  [C_0402]  171.84 50.15 180 top
CMOS1  SHORT PADS~D  [SHORTPADS]  152.07 55.3 180 bottom
CS5  1000P_0402_50V7K  [C_0402]  189.11 26.47 90 bottom
CS6  0.1U_0402_25V6K  [C_0402]  188.24 26.47 90 bottom
CS7  10U_0805_10V6K  [C_0805]  183.13 27.49 90 bottom
CS27  0.01U_0402_16V7K  [C_0402]  172.29 17.27 270 top
CS28  0.1U_0402_25V6K  [C_0402]  138.02 27.74 0 top
CS29  0.1U_0402_25V6K  [C_0402]  168.05 24.74 90 top
CS30  0.01U_0402_16V7K  [C_0402]  173.84 22.28 0 top
CS31  0.01U_0402_16V7K  [C_0402]  173.84 20.37 0 top
CS32  0.01U_0402_16V7K  [C_0402]  173.84 21.39 0 top
CS33  0.01U_0402_16V7K  [C_0402]  165.33 20.37 0 top
CS34  0.01U_0402_16V7K  [C_0402]  173.84 19.48 0 top
CS35  0.01U_0402_16V7K  [C_0402]  165.33 19.48 0 top
CS36  0.01U_0402_16V7K  [C_0402]  165.33 21.39 0 top
CS37  0.01U_0402_16V7K  [C_0402]  165.33 22.28 0 top
CV15  10U_0603_6.3V6M  [C_0603]  43.11 71.87 270 top
CV16  10U_0603_6.3V6M  [C_0603]  57.52 78.79 0 top
CV24  4.7U_0603_6.3V6K  [C_0603]  64.38 91.37 0 top
CV30  0.1U_0402_10V7K  [C_0402]  69.91 92 0 top
CV32  22U_0603_6.3V6M  [C_0603]  60.95 76.38 0 top
CV33  22U_0603_6.3V6M  [C_0603]  73.4 88 270 top
CV34  18P_0402_50V8J  [C_0402]  74.17 106 270 bottom
CV35  18P_0402_50V8J  [C_0402]  77.82 103.62 0 bottom
CV36  22U_0603_6.3V6M  [C_0603]  87.81 105.91 270 bottom
CV39  10U_0603_6.3V6M  [C_0603]  60.82 91.37 0 top
CV40  0.1U_0402_10V7K  [C_0402]  67.37 92.69 90 top
CV42  10U_0603_6.3V6M  [C_0603]  30.03 105.02 90 top
CV43  22U_0603_6.3V6M  [C_0603]  59.36 87.75 270 top
CV45  0.1U_0402_10V7K  [C_0402]  57.64 92 0 top
CV46  22U_0603_6.3V6M  [C_0603]  72.95 89.65 90 top
CV47  4.7U_0603_6.3V6K  [C_0603]  59.36 91.05 270 top
CV48  0.1U_0402_10V7K  [C_0402]  57.66 86.92 180 top
CV49  0.1U_0402_10V7K  [C_0402]  70.67 88.14 270 top
CV50  1U_0402_6.3V6K  [C_0402]  203.38 112.5 90 bottom
CV51  12P_0402_50V8J  [C_0402]  201.27 117.54 270 top
CV52  12P_0402_50V8J  [C_0402]  201.47 110.78 90 top
CV53  12P_0402_50V8J  [C_0402]  201.48 104.94 90 top
CV54  3.3P_0402_50V8C  [C_0402]  203.38 116.93 90 top
CV55  3.3P_0402_50V8C  [C_0402]  204.01 111.7 270 top
CV56  3.3P_0402_50V8C  [C_0402]  203.57 105.86 270 top
CV57  0.1U_0402_25V6  [C_0402]  204.46 105.86 270 top
CV58  22P_0402_50V8J  [C_0402]  203.38 110.49 270 bottom
CV59  22P_0402_50V8J  [C_0402]  203.38 115.67 90 bottom
CV60  12P_0402_50V8J  [C_0402]  198.3 107.32 270 top
CV61  12P_0402_50V8J  [C_0402]  199.45 112.82 90 top
CV62  12P_0402_50V8J  [C_0402]  199.86 115.51 270 top
CV63  0.1U_0402_10V7K  [C_0402]  67.42 81.08 0 top
CV64  0.1U_0402_10V7K  [C_0402]  69.32 80.7 0 top
CV65  4.7U_0603_6.3V6K  [C_0603]  60 80.51 270 top
CV68  0.1U_0402_10V7K  [C_0402]  68.25 93.02 0 top
CV112  4.7U_0603_6.3V6K  [C_0603]  72.13 88 270 top
CV129  0.1U_0402_10V7K  [C_0402]  76.71 82.86 180 top
CV130  4.7U_0603_6.3V6K  [C_0603]  70.29 91.05 270 top
CV131  1U_0402_6.3V6K  [C_0402]  39.93 105.13 90 top
CV132  1U_0402_6.3V6K  [C_0402]  38.28 105.13 90 bottom
CV133  0.1U_0402_10V7K  [C_0402]  61.95 93.02 0 top
CV134  0.1U_0402_10V7K  [C_0402]  71.81 89.64 90 top
CV135  4.7U_0603_6.3V6K  [C_0603]  62.79 80.63 270 top
CV136  10U_0603_6.3V6M  [C_0603]  30.03 105.02 90 bottom
CV139  0.1U_0402_10V7K  [C_0402]  84.33 103.3 180 bottom
CV140  1000P_0402_50V7K  [C_0402]  84.33 101.91 180 bottom
CV141  470P_0402_50V7K  [C_0402]  84.33 101.02 180 bottom
CV142  0.1U_0402_10V7K  [C_0402]  83.42 100.13 0 bottom
CV143  0.1U_0402_10V6K  [C_0402]  41.58 105.13 90 top
CV151  0.1U_0402_10V6K  [C_0402]  41.58 105.13 90 bottom
CV158  10U_0603_6.3V6M  [C_0603]  36.38 71.49 270 bottom
CV159  4.7U_0603_6.3V6K  [C_0603]  73.52 79.56 0 top
CV160  4.7U_0603_6.3V6K  [C_0603]  73.52 81.08 0 top
CV161  0.1U_0402_10V7K  [C_0402]  58.65 85.4 0 top
CV163  0.1U_0402_10V7K  [C_0402]  58.78 82.98 0 top
CV164  4.7U_0603_6.3V6K  [C_0603]  75.3 92.89 0 top
CV165  1U_0402_6.3V6K  [C_0402]  58.78 88.7 0 top
CV168  1U_0402_6.3V6K  [C_0402]  51.57 96.19 180 top
CV170  1U_0402_6.3V6K  [C_0402]  31.55 72.01 270 top
CV172  0.1U_0402_10V6K  [C_0402]  38.28 105.13 90 top
CV173  1U_0402_6.3V6K  [C_0402]  39.17 72.01 270 bottom
CV174  0.1U_0402_10V6K  [C_0402]  31.68 105.01 90 bottom
CV178  1U_0402_6.3V6K  [C_0402]  39.93 105.13 90 bottom
CV179  1U_0402_6.3V6K  [C_0402]  34.6 105.01 90 top
CV180  0.1U_0402_10V6K  [C_0402]  37.65 72.01 270 top
CV181  0.1U_0402_10V6K  [C_0402]  31.55 72.01 270 bottom
CV183  1U_0402_6.3V6K  [C_0402]  43.24 105.13 90 bottom
CV184  1U_0402_6.3V6K  [C_0402]  43.24 105.13 90 top
CV186  1U_0402_6.3V6K  [C_0402]  33.2 105.01 90 top
CV187  1U_0402_6.3V6K  [C_0402]  31.68 105.01 90 top
CV188  0.22U_0402_16V7K  [C_0402]  72.5 76.25 0 top
CV189  0.22U_0402_16V7K  [C_0402]  72.5 75.36 0 top
CV190  0.22U_0402_16V7K  [C_0402]  72.5 74.48 0 top
CV191  0.22U_0402_16V7K  [C_0402]  72.5 73.59 0 top
CV192  0.22U_0402_16V7K  [C_0402]  72.5 72.7 0 top
CV193  0.22U_0402_16V7K  [C_0402]  72.5 71.81 0 top
CV194  0.22U_0402_16V7K  [C_0402]  72.5 70.92 0 top
CV195  0.22U_0402_16V7K  [C_0402]  72.5 70.03 0 top
CV196  1U_0402_6.3V6K  [C_0402]  37.65 72.01 270 bottom
CV197  1U_0402_6.3V6K  [C_0402]  40.95 72.01 270 top
CV198  1U_0402_6.3V6K  [C_0402]  69.14 91.06 270 top
CV199  1U_0402_6.3V6K  [C_0402]  65.46 92.64 90 top
CV203  0.1U_0402_10V6K  [C_0402]  29.01 72.01 270 bottom
CV204  0.1U_0402_10V6K  [C_0402]  29.01 72.01 270 top
CV205  1U_0402_6.3V6K  [C_0402]  64.32 80.65 270 top
CV208  1U_0402_6.3V6K  [C_0402]  30.28 72.01 270 bottom
CV209  1U_0402_6.3V6K  [C_0402]  39.17 72.01 270 top
CV210  1U_0402_6.3V6K  [C_0402]  30.28 72.01 270 top
CV211  1U_0402_6.3V6K  [C_0402]  57.71 81.26 90 top
CV215  1U_0402_6.3V6K  [C_0402]  40.95 72.01 270 bottom
CV216  0.01U_0402_25V7K  [C_0402]  33.79 71.94 180 top
CV217  0.01U_0402_25V7K  [C_0402]  38.03 85.07 90 top
CV218  0.01U_0402_25V7K  [C_0402]  35.67 69.14 0 top
CV326  0.01U_0402_25V7K  [C_0402]  33.79 105.08 180 bottom
CV334  0.01U_0402_25V7K  [C_0402]  37.09 105.08 180 bottom
CV335  0.01U_0402_25V7K  [C_0402]  36.05 107.88 0 top
CV336  0.1U_0402_25V6  [C_0402]  191.96 112.95 90 bottom
CV337  0.1U_0402_25V6  [C_0402]  191.32 106.78 90 top
CV338  0.1U_0402_25V6  [C_0402]  194.19 105.99 270 bottom
CV339  0.1U_0402_25V6  [C_0402]  193.3 105.99 270 bottom
CV340  10U_0603_6.3V6M  [C_0603]  185.55 112.7 90 bottom
CV341  0.1U_0402_25V6  [C_0402]  193.37 108.6 0 bottom
CV342  0.1U_0402_10V7K  [C_0402]  181.92 105.53 0 bottom
CV343  0.1U_0402_25V6  [C_0402]  190.19 112.95 90 bottom
CV344  20P_0402_50V8J  [C_0402]  180.5 111.81 0 bottom
CV345  20P_0402_50V8J  [C_0402]  182.36 111.81 0 bottom
CV346  0.1U_0402_10V7K  [C_0402]  181.92 106.42 0 bottom
CV347  0.1U_0402_10V7K  [C_0402]  181.92 107.31 0 bottom
CV348  0.1U_0402_10V7K  [C_0402]  181.92 108.2 0 bottom
CV349  0.1U_0402_10V7K  [C_0402]  186.95 101.77 90 bottom
CV350  0.1U_0402_10V7K  [C_0402]  187.84 101.77 90 bottom
CV351  1U_0402_6.3V6K  [C_0402]  184.28 102.68 270 bottom
CV352  0.1U_0402_25V6  [C_0402]  186.06 102.68 270 bottom
CV353  0.1U_0402_25V6  [C_0402]  182.83 104.64 180 bottom
CV354  0.1U_0402_25V6  [C_0402]  182.83 109.09 180 bottom
CV355  0.1U_0402_25V6  [C_0402]  185.17 102.68 270 bottom
CV356  0.1U_0402_25V6  [C_0402]  190.43 104.28 90 top
CV357  0.1U_0402_25V6  [C_0402]  184.51 112.95 90 bottom
CV358  1U_0402_6.3V6K  [C_0402]  192.85 112.95 90 bottom
CV359  4.7U_0402_6.3V6M  [C_0402]  189.35 104.32 90 top
CV360  1U_0402_6.3V6K  [C_0402]  193.35 107.43 0 bottom
CV361  22U_0603_6.3V6M  [C_0603]  186.49 110.57 180 top
CX2  0.1U_0402_10V7K  [C_0402]  7.87 90.85 90 top
CX3  10U_0805_10V6K  [C_0805]  9.26 90.45 90 top
CX4  1000P_0402_50V7K  [C_0402]  5.62 77.95 0 top
CX5  0.1U_0603_25V7K  [C_0603]  2.91 81.21 0 top
CX6  0.1U_0402_10V7K  [C_0402]  3.17 90.78 90 top
CX7  4.7U_0805_10V4Z  [C_0805]  11.89 81.33 180 top
CX8  4.7U_0805_10V4Z  [C_0805]  12.06 90.45 90 top
CX10  0.1U_0402_10V7K  [C_0402]  2.28 90.78 90 top
CX11  0.1U_0402_10V7K  [C_0402]  10.66 90.85 90 top
CX12  0.1U_0402_10V7K  [C_0402]  195.08 65.2 180 bottom
CX13  0.1U_0402_10V7K  [C_0402]  195.08 66.22 180 bottom
CX14  0.1U_0402_10V7K  [C_0402]  195.08 62.41 180 bottom
CX15  0.1U_0402_10V7K  [C_0402]  195.08 63.43 180 bottom
CX16  0.1U_0402_10V7K  [C_0402]  195.08 67.87 180 bottom
CX17  0.1U_0402_10V7K  [C_0402]  195.08 68.89 180 bottom
CX18  0.1U_0402_10V7K  [C_0402]  195.08 70.54 180 bottom
CX19  0.1U_0402_10V7K  [C_0402]  195.08 71.55 180 bottom
CX20  0.1U_0402_10V7K  [C_0402]  3.12 85.84 180 top
CX21  0.1U_0402_10V7K  [C_0402]  199.95 63.35 90 top
CX22  10U_0603_6.3V6M  [C_0603]  198.87 62.28 180 top
CX23  3.3P_0402_50V8C  [C_0402]  200.54 65.25 270 bottom
CX24  3.3P_0402_50V8C  [C_0402]  200.54 66.12 90 bottom
CX25  3.3P_0402_50V8C  [C_0402]  199.65 62.46 270 bottom
CX26  3.3P_0402_50V8C  [C_0402]  199.65 63.32 90 bottom
CX27  3.3P_0402_50V8C  [C_0402]  199.65 67.92 270 bottom
CX28  3.3P_0402_50V8C  [C_0402]  199.65 68.79 90 bottom
CX29  3.3P_0402_50V8C  [C_0402]  200.59 70.61 270 bottom
CX30  3.3P_0402_50V8C  [C_0402]  200.59 71.48 90 bottom
CX31  0.1U_0402_25V6  [C_0402]  3.41 82.35 0 top
CX49  4.7U_0805_10V4Z  [C_0805]  12.77 99.46 270 top
CX50  0.1U_0402_10V7K  [C_0402]  14.57 99.34 270 top
CX51  4.7U_0805_10V4Z  [C_0805]  14.44 105.59 0 top
CZ49  1U_0402_6.3V6K  [C_0402]  16.92 64.65 0 top
CZ50  1U_0402_6.3V6K  [C_0402]  16.92 65.57 0 top
CZ51  1U_0402_6.3V6K  [C_0402]  16.92 66.47 0 top
D1  -  [RB751S40T1G_SOD523-2]  11.74 75.43 90 bottom
DA8  -  [BAT54CW_SOT323-3]  173.38 8.75 270 top
DA10  AZ5125-02S.R7G_SOT23-3  [AZ5125-02SPR7G_SOT23-3]  195.85 19.78 0 bottom
DA12  AZ5123-01F.R7G DFN1006P2X  [ESD207-B1-02EL_TSLP-2-19-2]  208.6 7.93 270 top
DA13  AZ5125-02S.R7G_SOT23-3  [AZ5125-02SPR7G_SOT23-3]  195.48 14.15 270 top
DA14  AZ5123-01F.R7G DFN1006P2X  [ESD207-B1-02EL_TSLP-2-19-2]  198.25 20.8 90 bottom
DC1  -  [BAT54CW_SOT323-3]  83.66 52.89 90 bottom
DE1  AZ5125-02S.R7G_SOT23-3  [AZ5125-02SPR7G_SOT23-3]  19.84 66.47 270 top
DE2  AZ5125-01H.R7G_SOD523-2  [AZ5125-01HPR7G_SOD523-2]  145.36 22.19 90 top
DE3  -  [PJDLC05C_SOT23-3]  11.38 53.08 270 bottom
DI1  IP4292CZ10-TBR_XSON10_2.5X1  [IP4292CZ10-TBR_XSON10_2P5X1]  196.95 50.2 270 bottom
DI2  -  [PJDLC05C_SOT23-3]  195.76 46.43 0 bottom
DI4  IP4292CZ10-TBR_XSON10_2.5X1  [IP4292CZ10-TBR_XSON10_2P5X1]  196.95 32.04 270 bottom
DI5  -  [PJDLC05C_SOT23-3]  196.91 27.23 270 bottom
DS1  -  [PJDLC05C_SOT23-3]  141.44 25.58 270 top
DV1  -  [BAT54CW_SOT323-3]  7.13 83.11 90 top
DV2  -  [BAT54CW_SOT323-3]  7.13 80.7 90 top
DV3  -  [RB751V-40_SOD323-2]  74.32 96.57 180 top
DV5  -  [PJDLC05C_SOT23-3]  201.55 114.16 270 top
DV6  -  [PJDLC05C_SOT23-3]  201.45 108.32 270 top
DV7  -  [BAT54CW_SOT323-3]  13.35 83.62 90 top
DX2  AZ5125-02S.R7G_SOT23-3  [AZ5125-02SPR7G_SOT23-3]  6.32 94.73 270 top
DX3  AZ5125-02S.R7G_SOT23-3  [AZ5125-02SPR7G_SOT23-3]  6.05 87.8 270 top
DX4  AZ5125-02S.R7G_SOT23-3  [AZ5125-02SPR7G_SOT23-3]  7.99 77.14 180 top
F1  0.5A_15V_SMD1206P050TF  [F_KMC3S050RY]  114.28 26.09 0 top
FD1  FIDUCAL  [FIDUCIAL_C40M80]  13.01 109.4 0 top
FD2  FIDUCIAL  [FIDUCIAL_C40M80]  174.43 15.29 0 top
FD3  FIDUCAL  [FIDUCIAL_C40M80]  205.54 100.26 180 bottom
FD4  FIDUCIAL  [FIDUCIAL_C40M80]  20.69 18.6 180 bottom
FX1  1.5A_8V_1206L150THWR  [F_1206L150THWR]  196.02 53.01 180 top
H1  -  [H_2P3]  27.8 121.75 0 top
H2  -  [H_2P8X3P1N]  33.25 122.85 90 top
H3  -  [H_2P8]  22.1 81.05 0 top
H4  -  [H_2P8]  21.8 12.75 90 top
H5  -  [H_6P6]  82.8 60.75 0 top
H6  -  [H_3P5]  107.3 104 0 top
H7  -  [H_3P2X3P5]  107.3 83.5 90 top
H8  -  [H_2P8]  101 6.45 0 top
H9  -  [H_3P2X3P5]  166.3 104 180 top
H10  -  [H_3P2]  166.3 83.5 0 top
H11  -  [H_2P8]  165.8 72.75 0 top
H12  -  [H_2P3N]  183.5 119.35 0 top
H14  -  [H_6P0]  196.2 100.35 0 top
H15  -  [H_3P2]  181.73 76.2 0 top
H17  -  [H_2P8]  183 35.05 0 top
H19  -  [H_2P8]  190.2 5.95 0 top
H20  -  [H_1P1N]  115.34 97.25 0 top
H21  -  [H_1P1N]  158.26 88.25 0 top
H22  -  [H_3P3]  87.18 112.57 0 top
H23  -  [H_3P3]  40.92 64.73 0 top
H24  -  [H_3P3]  6.4 106.7 0 top
JBATT  LLTOP_ALLTOP C144LS-109A9-L 9P BATT P2  [ALLTO_C144LS-109A9-L_9P-T]  14.15 15.47 90 bottom
JCRT  C-K_80443A-5K1-152  [C-K_80443A-5K1-152_15P]  207.7 118.5 270 bottom
JDCIN  ACES_50299-00501-003  [ACES_50299-00501-003_5P]  19.5 114.15 90 top
JDEG  ACES_87153-10411  [ACES_87153-10411_10P]  67.35 19.66 0 bottom
JDIMM1  FOX_AS0A621-U4R6-7H  [FOX_AS0A621-U4R6-7H_204P]  96.15 50.04 180 bottom
JDIMM2  FOX_AS0A621-U4S6-7H  [FOX_AS0A621-U4S6-7H_204P]  108.15 37.07 0 bottom
JEDP  ACES_50398-04041-001  [ACES_50398-04041-001_40P]  3.28 80.95 90 bottom
JFAN  ACES_50279-0040N-001  [ACES_50279-0040N-001_4P]  8.31 74.98 180 bottom
JFP  E-T_6916K-Q06N-00L  [ACES_51524-0060N-001_6P]  131.05 27.1 0 top
JHDD  ACES_50208-01001-001  [ACES_50208-01001-001_10P]  187.24 21.35 180 bottom
JHDMI  CONCR_099ATAC19NBLCNF  [CONCR_099ATAC19NBLCNF_19P]  203.85 72.55 270 bottom
JHP  SINGA_2SJ3080-001111F  [SINGA_2SJ3080-001111F_6P]  201.75 19.74 90 bottom
JIO  ACES_51524-0160N-001  [ACES_51524-0160N-001_16P]  25.75 46.9 90 bottom
JKB  ACES_51510-0304N-P01  [ACES_51510-0304N-P01_30P]  91.95 50.7 270 top
JKBBL  ACES_50524-00401-P01  [ACES_50524-00401-P01_4P]  120.37 19.75 270 top
JLAN  J-L_TNBNRAC80015008  [J-L_TNBNRAC80015008_8P]  201.1 92.07 270 bottom
JLED  ACES_51524-0080N-001  [ACES_51524-0080N-001_8P]  14.7 60.35 270 top
JLPDE  ACES_87153-10411  [ACES_87153-10411_10P]  67.35 13.91 0 bottom
JNGFF  LOTES_APCI0019-P009A  [LOTES_APCI0019-P009A_67P]  172.48 42.68 0 bottom
JRTC  ACES_50271-0020N-001  [ACES_50271-0020N-001_2P]  82.6 48.95 180 bottom
JSPK  ACES_50278-00401-001  [ACES_50278-00401-001_4P]  208.9 7.6 180 bottom
JTAG1  @SHORT PADS~D  [SHORTPADS]  149.03 25.71 90 top
JTP  ACES_51524-0080N-001  [ACES_51524-0080N-001_8P]  20.68 63.17 0 top
JUSB1  TAITW_PUBAU6-09FLBS1NN4H0  [TAITW_PUBAU6-09FLBS1NN4H0_9P]  199.59 44.6 270 bottom
JUSB2  TAITW_PUBAU6-09FLBS1NN4H0  [TAITW_PUBAU6-09FLBS1NN4H0_9P]  199.59 26.4 270 bottom
JXDP  SAMTE_BSH-030-01-L-D-A  [SAMTE_BSH-030-01-L-D-A_60P]  91.37 68.66 90 top
L1  2.2UH_LQM2MPN2R2NG0L_30%  [MURAT_LQM2MPN2R2NG0L_2P]  147.25 115.15 270 bottom
L2  2.2UH_LQM2MPN2R2NG0L_30%  [MURAT_LQM2MPN2R2NG0L_2P]  147.76 115.46 90 top
L3  2.2UH_LQM2MPN2R2NG0L_30%  [MURAT_LQM2MPN2R2NG0L_2P]  135.98 92 180 top
L4  2.2UH_LQM2MPN2R2NG0L_30%  [MURAT_LQM2MPN2R2NG0L_2P]  145.47 115.46 90 top
L5  2.2UH_LQM2MPN2R2NG0L_30%  [MURAT_LQM2MPN2R2NG0L_2P]  139.12 114.77 270 top
L12  DLW21HN900HQ2L_4P  [MURAT_DLW21HN900HQ2L_4P]  147.08 25.88 180 top
L18  2.2UH_NLC252018T-2R2J-N_5%  [CHILI_NLC252018T-2R2J-N_2P]  176.84 92.9 270 bottom
LA1  BLM15BB221SN1D_2P  [MURAT_BLM15BB221SN1D_2P]  181.29 21.82 180 top
LA8  MURATA BLM15AX700SN1D_2P  [MURAT_BLM15BB221SN1D_2P]  194.23 22.41 180 bottom
LA9  MURATA BLM15AX700SN1D_2P  [MURAT_BLM15BB221SN1D_2P]  193.41 18.4 180 bottom
LA10  BLM15PX330SN1D_2P  [MURAT_BLM15PX330SN1D_2P]  193 13.78 180 bottom
LA11  BLM15PX330SN1D_2P  [MURAT_BLM15PX330SN1D_2P]  193.03 15.36 180 bottom
LI1  CMMI21T-670Y-N_4P  [MURAT_DLW21SN670HQ2L_4P]  196.67 54.15 270 bottom
LI2  DLW21HN900HQ2L_4P  [MURAT_DLW21HN900HQ2L_4P]  194.93 40.73 90 bottom
LI3  CMMI21T-670Y-N_4P  [MURAT_DLW21SN670HQ2L_4P]  195.02 54.15 270 bottom
LI4  CMMI21T-670Y-N_4P  [MURAT_DLW21SN670HQ2L_4P]  192.5 32.08 0 bottom
LI5  DLW21HN900HQ2L_4P  [MURAT_DLW21HN900HQ2L_4P]  190.98 27.81 0 bottom
LI6  CMMI21T-670Y-N_4P  [MURAT_DLW21SN670HQ2L_4P]  192.5 30.43 0 bottom
LV8  HCB1608KF-181T20_0603  [TAI-T_HCB1608KF-121T3_L0603_2P]  76.36 88.19 180 top
LV10  BLM18PG300SN1D_2P  [MURAT_BLM18PG300SN1D_2P]  75.33 89.97 180 top
LV14  BLM15PD600SN1D_2P  [MURAT_BLM15PD600SN1D_2P]  182 103.62 0 bottom
LV15  BLM15PD600SN1D_2P  [MURAT_BLM15PD600SN1D_2P]  194.17 111.43 180 bottom
LV16  BLM15BB470SN1D_2P  [MURAT_BLM15BB470SN1D_2P]  202.32 117.51 270 top
LV17  BLM15BB470SN1D_2P  [MURAT_BLM15BB470SN1D_2P]  202.37 111.24 0 top
LV18  BLM15BB470SN1D_2P  [MURAT_BLM15BB470SN1D_2P]  202.49 105.02 90 top
LV19  BLM15AG121SN1D_L0402_2P  [MURAT_BLM15AG121SN1D_L0402_2P]  200.67 116.13 0 bottom
LV20  BLM15AG121SN1D_L0402_2P  [MURAT_BLM15AG121SN1D_L0402_2P]  200.67 110.04 0 bottom
LV21  BLM15PD600SN1D_2P  [MURAT_BLM15PD600SN1D_2P]  195.88 106.16 180 bottom
LV26  BLM18PG300SN1D_2P  [MURAT_BLM18PG300SN1D_2P]  58.76 76.51 0 top
LX1  FBMA-L11-201209-221LMA30_2P  [KC_FBMA-L11-201209-221LMA30_2P]  15.41 88.89 90 top
LX2  DLW21HN900HQ2L_4P  [MURAT_DLW21HN900HQ2L_4P]  196.82 66.16 0 bottom
LX3  DLW21HN900HQ2L_4P  [MURAT_DLW21HN900HQ2L_4P]  196.82 63.37 0 bottom
LX4  DLW21HN900HQ2L_4P  [MURAT_DLW21HN900HQ2L_4P]  196.82 68.83 0 bottom
LX5  DLW21HN900HQ2L_4P  [MURAT_DLW21HN900HQ2L_4P]  196.82 71.5 0 bottom
LX6  DLW21HN900HQ2L_4P  [MURAT_DLW21HN900HQ2L_4P]  12.43 88.91 180 top
LX7  DLW21HN900HQ2L_4P  [MURAT_DLW21HN900HQ2L_4P]  13.23 95.16 180 top
LX8  CMMI21T-670Y-N_4P  [MURAT_DLW21SN670HQ2L_4P]  7.91 102.82 180 top
LX9  CMMI21T-670Y-N_4P  [MURAT_DLW21SN670HQ2L_4P]  7.92 100.53 180 top
LX10  CMMI21T-670Y-N_4P  [MURAT_DLW21SN670HQ2L_4P]  7.94 98.24 180 top
NOREF  -  []  107.3 104 0 top
NOREF#2  -  []  101 6.45 0 top
NOREF#3  -  []  101 6.45 0 top
NOREF#4  -  []  87.18 112.57 0 top
NOREF#5  -  []  102.62 -35 0 top
NOREF#6  -  []  181.73 76.2 0 top
NOREF#7  -  []  1.48 173.92 0 top
NOREF#8  -  []  40.92 64.73 0 top
NOREF#9  -  []  181.73 76.2 0 top
NOREF#10  -  []  166.3 104 0 top
NOREF#11  -  []  148.61 66.83 0 top
NOREF#12  -  []  165.8 72.75 0 top
NOREF#13  -  []  183 35.05 0 top
NOREF#14  -  []  6.4 106.7 0 top
NOREF#15  -  []  166.3 104 0 top
NOREF#16  -  []  113.87 173.79 0 top
NOREF#17  -  []  107.3 83.5 0 top
NOREF#18  -  []  165.8 72.75 0 top
NOREF#19  -  []  166.3 83.5 0 top
NOREF#20  -  []  183.5 119.35 0 top
NOREF#21  -  []  107.3 83.5 0 top
NOREF#22  -  []  150.46 55.62 0 top
NOREF#23  -  []  27.8 121.75 0 top
NOREF#24  -  []  22.1 81.05 0 top
NOREF#25  -  []  107.3 104 0 top
NOREF#26  -  []  82.8 60.75 0 top
NOREF#27  -  []  21.8 12.75 0 top
NOREF#28  -  []  166.3 83.5 0 top
NOREF#29  -  []  146.19 51.48 0 top
NOREF#30  -  []  21.8 12.75 0 top
NOREF#31  -  []  22.1 81.05 0 top
NOREF#32  -  []  183 35.05 0 top
NOREF#33  -  []  27.8 121.75 0 top
NOREF#34  -  []  98.6 75.71 0 top
NOREF#35  -  []  82.8 60.75 0 top
NOREF#36  -  []  190.2 5.95 0 top
NOREF#37  -  []  196.2 100.35 0 top
NOREF#38  -  []  201.4 78.65 0 top
NOREF#39  -  []  120.07 118.32 0 top
NOREF#40  -  []  163.89 17.9 180 bottom
NOREF#41  -  []  159.31 68.15 180 bottom
NOREF#42  -  []  153.83 74.03 180 bottom
NOREF#43  -  []  135.12 71.3 180 bottom
PC1  1000P_0402_50V7K  [C_0402]  18.85 34.01 90 top
PC2  2200P_0402_50V7K  [C_0402]  18.28 27.6 90 top
PC3  0.01U_0402_25V7K  [C_0402]  21.01 34.01 90 top
PC5  1000P_0603_50V7K  [C_0603]  21.52 119.94 0 bottom
PC9  1000P_0402_50V7K  [C_0402]  19.87 118.62 270 bottom
PC10  100P_0402_50V8J  [C_0402]  18.98 118.62 270 bottom
PC11  0.1U_0402_25V6  [C_0402]  38.69 120.21 0 top
PC16  100P_0402_50V8J  [C_0402]  26.43 109.63 180 top
PC17  1000P_0402_50V7K  [C_0402]  14.53 41.33 90 bottom
PC18  10U_0805_25V6K  [C_0805]  26.74 110.94 180 top
PC100  4.7U_0603_6.3V6K  [C_0603]  55.43 23.36 90 top
PC101  220U_6.3V_M  [C_APXK6R3ARA221MF451]  51.36 37.87 270 bottom
PC102  100P_0402_50V8J  [C_0402]  55.83 29.67 180 bottom
PC103  680P_0603_50V8J  [C_0603]  48.15 33.39 270 top
PC104  0.1U_0402_25V6  [C_0402]  52.13 32.23 90 top
PC105  1U_0603_25V6K  [C_0603]  49.71 29.25 270 bottom
PC106  4.7U_0603_10V6K  [C_0603]  47.74 28.31 270 top
PC107  220U_6.3V_M  [C_APXK6R3ARA221MF451]  51.55 18.34 90 bottom
PC108  100P_0402_50V8J  [C_0402]  55 27.33 0 bottom
PC109  4.7U_0603_10V6K  [C_0603]  55 28.6 0 top
PC110  0.1U_0402_25V6  [C_0402]  52 23.9 90 top
PC111  680P_0603_50V8J  [C_0603]  48.19 22.34 90 top
PC112  10U_0805_25V6K  [C_0805]  43.74 28.37 0 bottom
PC113  0.1U_0402_25V7K  [C_0402]  43.67 26.85 0 top
PC114  2200P_0402_50V7K  [C_0402]  43.54 29.77 0 top
PC115  10U_0805_25V6K  [C_0805]  43.78 28.37 0 top
PC116  150U_D2_6.3VM_R17M  [C_D2-NPM]  50.86 38.5 270 bottom
PC117  150U_D2_6.3VM_R17M  [C_D2-NPM]  51.06 17.54 90 bottom
PC200  0.1U_0603_25V7K  [C_0603]  62.67 33.64 90 bottom
PC201  2200P_0402_50V7K  [C_0402]  71.05 36.55 90 top
PC202  0.1U_0402_10V7K  [C_0402]  56.94 32.8 0 top
PC203  0.1U_0402_10V7K  [C_0402]  56.94 31.91 0 top
PC204  1U_0603_10V6K  [C_0603]  57 37.12 0 top
PC205  10U_0805_6.3V6K  [C_0805]  60.72 28.76 180 bottom
PC206  10U_0805_25V6K  [C_0805]  69.96 37.01 180 bottom
PC207  680P_0402_50V7K  [C_0402]  62.59 36.88 0 top
PC208  0.1U_0402_25V6  [C_0402]  71.02 39.65 270 bottom
PC209  1U_0603_10V6K  [C_0603]  58.4 37.12 180 bottom
PC210  0.033U_0402_16V7K  [C_0402]  57.83 28.29 270 bottom
PC211  10U_0805_6.3V6K  [C_0805]  62.16 28.34 270 bottom
PC212  10U_0805_25V6K  [C_0805]  69.99 37.01 180 top
PC214  330U_2.5V_M  [C_MP6VU330MC6]  74.01 30 90 bottom
PC299  330U_D2_2V_Y  [C_D2-NPM]  74.01 29.61 90 bottom
PC300  0.22U_0402_10V6K  [C_0402]  102.4 121.39 90 bottom
PC301  680P_0603_50V7K  [C_0603]  99.92 113.21 180 bottom
PC302  0.1U_0603_25V7K  [C_0603]  97.78 117.21 0 top
PC303  2200P_0402_50V7K  [C_0402]  94.6 117.4 180 bottom
PC304  0.1U_0402_25V6  [C_0402]  94.6 116.51 180 bottom
PC305  10U_0805_25V6K  [C_0805]  95.64 113.46 0 bottom
PC306  10U_0805_25V6K  [C_0805]  95.64 115.17 0 bottom
PC307  330P_0402_50V7K  [C_0402]  98.16 121.72 180 bottom
PC308  47U_0805_6.3V6M  [C_0805]  109.53 114.89 270 bottom
PC309  47U_0805_6.3V6M  [C_0805]  106.93 113.65 180 bottom
PC310  22U_0805_6.3VAM  [C_0805]  106.99 122.03 180 bottom
PC311  22U_0805_6.3VAM  [C_0805]  109.87 122.02 0 bottom
PC312  4.7U_0603_6.3V6K  [C_0603]  96.24 121.02 90 bottom
PC313  4.7U_0603_6.3V6K  [C_0603]  94.4 118.48 90 bottom
PC400  1U_0402_6.3V6K  [C_0402]  178.49 117.27 0 bottom
PC401  4.7U_0805_6.3V6K  [C_0805]  177 119.75 0 bottom
PC402  0.1U_0402_16V7K  [C_0402]  178.41 114.86 0 bottom
PC403  0.01U_0402_25V7K  [C_0402]  169.14 114.29 0 bottom
PC404  22U_0805_6.3V6M  [C_0805]  169.6 118.38 270 bottom
PC500  1000P_0402_50V7K  [C_0402]  66.49 104.51 180 bottom
PC510  47P_0402_50V8J  [C_0402]  67.37 103.74 90 bottom
PC515  100U_25V_M  [C_EEEFZ1E101P-NPM]  46.54 113.5 90 bottom
PC516  100U_25V_M  [C_EEEFZ1E101P-NPM]  53.65 113.5 90 bottom
PC517  10U_0805_25V6K  [C_0805]  57.52 110.12 270 bottom
PC518  10U_0805_25V6K  [C_0805]  55.74 110.12 270 bottom
PC519  0.1U_0402_25V7K  [C_0402]  54.35 109.92 270 bottom
PC520  680P_0603_50V7K  [C_0603]  65.97 119.37 180 top
